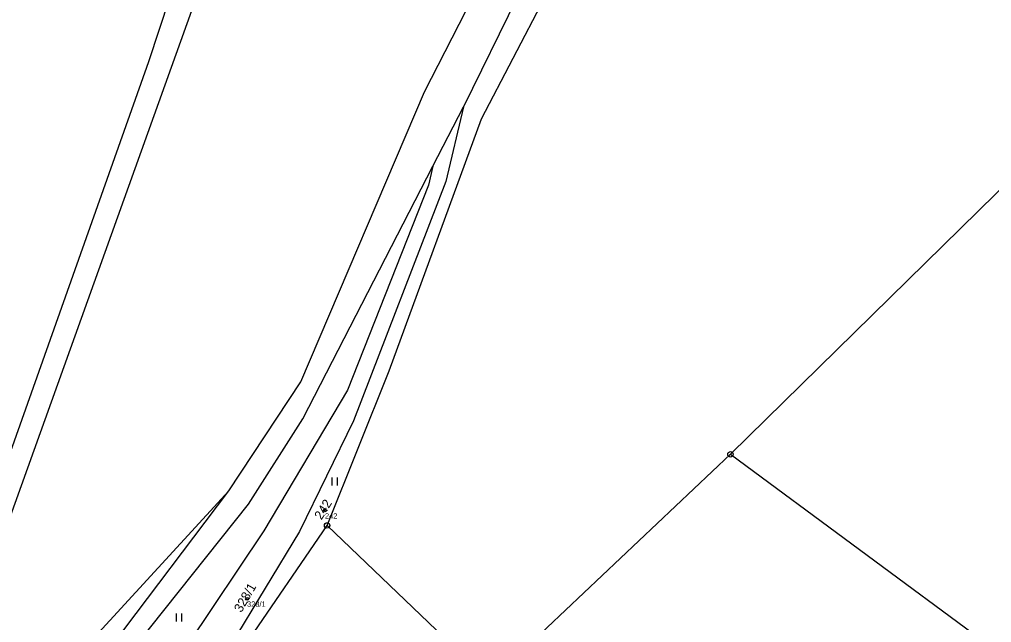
# Model space of a CAD drawing. Extents: x -867966 to -864255, y -1043242 to -1041327.
# Drawn here: x -865091.7 to -864912.2, y -1042286.1 to -1042174.8 of the extents above; entities that cross this region are included whole.
import ezdxf

# ---------------------------------------------------------------- set-up
doc = ezdxf.new("R2010")
doc.units = 0
for name, color, linetype in [('Definiční body', 7, 'Continuous'), ('Hranice parcel', 7, 'Continuous'), ('Parcelní čísla', 7, 'Continuous'), ('Značky bodu BP', 7, 'Continuous'), ('Značky kultur', 7, 'Continuous')]:
    doc.layers.add(name, color=color, linetype=linetype)

msp = doc.modelspace()

# ---------------------------------------------------------------- linework, layer by layer
at = {"layer": 'Definiční body'}
for centre in [(-865035.26, -1042265.45), (-865049.65, -1042281.72)]:
    msp.add_circle(centre, 0.25, dxfattribs=at)
at = {"layer": 'Hranice parcel'}
for p, q in [((-865016.88, -1042188.18), (-864974.64, -1042105.62)), ((-865037.52, -1042110.65), (-865063.63, -1042183.64)), ((-864976.42, -1042123.35), (-865009.7, -1042190.9)), ((-865006.32, -1042193.16), (-864971.87, -1042127.01)), ((-865067.76, -1042182.54), (-865053.33, -1042138.42)), ((-865102.25, -1042279.75), (-865067.76, -1042182.54)), ((-865063.63, -1042183.64), (-865098.95, -1042281.95)), ((-865039.69, -1042241.7), (-865016.88, -1042188.18)), ((-865015.34, -1042201.88), (-865009.7, -1042190.9)), ((-865009.7, -1042190.9), (-865012.94, -1042204.72)), ((-865023.37, -1042239.67), (-865006.32, -1042193.16)), ((-864900.11, -1042195.91), (-864960.38, -1042255.07)), ((-865039.37, -1042248.5), (-865015.34, -1042201.88)), ((-865015.34, -1042201.88), (-865016.11, -1042205.41)), ((-865016.11, -1042205.41), (-865031.09, -1042243.24)), ((-865012.94, -1042204.72), (-865030, -1042248.88)), ((-865034.85, -1042268.2), (-865023.37, -1042239.67)), ((-865052.99, -1042261.83), (-865039.69, -1042241.7)), ((-865031.09, -1042243.24), (-865046.56, -1042269.22)), ((-865049.38, -1042264.29), (-865039.37, -1042248.5)), ((-865030, -1042248.88), (-865039.94, -1042269.34)), ((-865004.74, -1042296.94), (-864960.38, -1042255.07)), ((-864960.38, -1042255.07), (-864906.19, -1042295)), ((-865052.99, -1042261.83), (-865080.75, -1042291.96)), ((-865077.61, -1042294.34), (-865052.99, -1042261.83)), ((-865073.47, -1042294.52), (-865049.38, -1042264.29)), ((-865051.69, -1042292.8), (-865034.85, -1042268.2)), ((-865034.85, -1042268.2), (-865004.74, -1042296.94)), ((-865039.94, -1042269.34), (-865072.4, -1042322.57)), ((-865046.56, -1042269.22), (-865065.99, -1042298.22))]:
    msp.add_line(p, q, dxfattribs=at)
at = {"layer": 'Značky bodu BP'}
for centre, radius in [((-864960.38, -1042255.07), 0.5), ((-864960.38, -1042255.07), 0.0303), ((-865034.85, -1042268.2), 0.5), ((-865034.85, -1042268.2), 0.0303)]:
    msp.add_circle(centre, radius, dxfattribs=at)
at = {"layer": 'Značky kultur'}
for p, q in [((-865033.94, -1042260.84), (-865033.94, -1042259.34)), ((-865032.94, -1042260.84), (-865032.94, -1042259.34)), ((-865062.66, -1042285.94), (-865062.66, -1042284.44)), ((-865061.66, -1042285.94), (-865061.66, -1042284.44))]:
    msp.add_line(p, q, dxfattribs=at)

# ---------------------------------------------------------------- texts
at = {"layer": 'Definiční body'}
for s, p in [('242', (-865035.26, -1042266.94)), ('328/1', (-865049.65, -1042283.21))]:
    msp.add_text(s, height=1, dxfattribs=at).set_placement(p)
at = {"layer": 'Parcelní čísla'}
for s, rotation, p in [('242', 58, (-865035.9, -1042267.28)), ('328/1', 60, (-865050.7, -1042284.39))]:
    msp.add_text(s, height=1.7, rotation=rotation, dxfattribs=at).set_placement(p)

doc.saveas('drawing.dxf')
